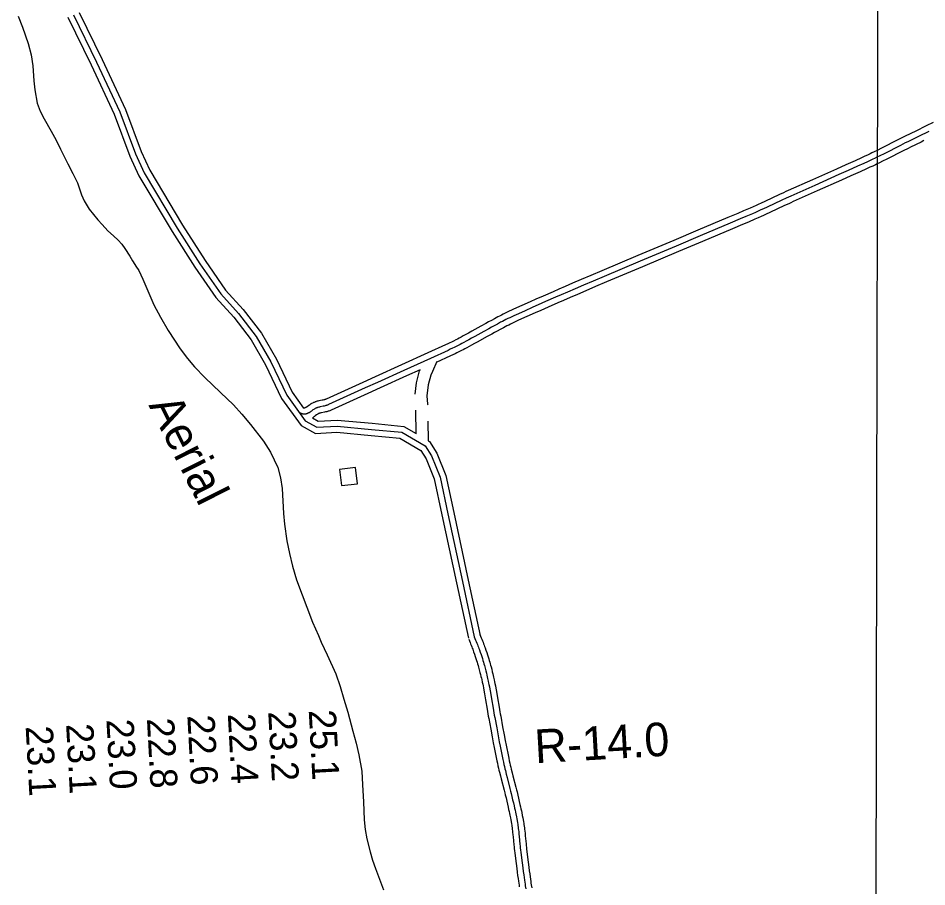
# Model space of a CAD drawing. Extents: x 3192952 to 3230831, y 849296 to 874698.
# Drawn here: x 3210734 to 3212978, y 863672 to 865816 of the extents above; entities that cross this region are included whole.
import ezdxf

# ---------------------------------------------------------------- set-up
doc = ezdxf.new("R2010")
doc.units = 0
for name, color, linetype in [('V-BLDG-OTLN', 7, 'Continuous'), ('V-GRID-MAJR', 7, 'Continuous'), ('V-RIVR-IDEN', 7, 'Continuous'), ('V-RIVR-RANG', 7, 'Continuous'), ('V-RIVR-RANG-IDEN', 7, 'Continuous'), ('V-ROAD-CNTR', 7, 'Continuous'), ('V-SITE-VEGE', 7, 'Continuous'), ('V-TOPO-SHOR', 7, 'Continuous')]:
    doc.layers.add(name, color=color, linetype=linetype)

msp = doc.modelspace()

# ---------------------------------------------------------------- linework, layer by layer
at = {"layer": 'V-BLDG-OTLN'}
msp.add_lwpolyline([(3211532.2, 864662), (3211571.9, 864666.8), (3211567.2, 864706.5), (3211527.4, 864701.7)], close=True, dxfattribs=at)
at = {"layer": 'V-GRID-MAJR'}
msp.add_spline([(3212836, 854703.6), (3212847.5, 860762.7), (3212858.9, 866825.2), (3212870.4, 872887.8), (3212870.4, 872891.2)], degree=3, dxfattribs=at)
at = {"layer": 'V-ROAD-CNTR'}
for p, q in [((3211715.3, 864847.9), (3211716.1, 864790.2)), ((3211745.6, 864821.4), (3211746.4, 864772.8))]:
    msp.add_line(p, q, dxfattribs=at)
for points in [[(3210884.3, 865829.6), (3210941.1, 865713.7), (3210999, 865590.2), (3211037.4, 865487), (3211058.8, 865440.8), (3211139.4, 865305.1), (3211195.4, 865217.9), (3211246, 865144.7), (3211289.3, 865096.8), (3211334.5, 865038.2), (3211371.5, 864974.3), (3211410.2, 864892.6), (3211438.8, 864853.2)], [(3210856.7, 865817.8), (3210914, 865700.8), (3210971.3, 865578.6), (3211009.7, 865475.4), (3211032.2, 865426.8), (3211113.9, 865289.3), (3211170.5, 865201.3), (3211222.4, 865126), (3211266.2, 865077.5), (3211309.5, 865021.5), (3211344.9, 864960.3), (3211384.3, 864877.2), (3211432.4, 864810.8), (3211467.9, 864790.9), (3211521, 864793.6), (3211605.2, 864786), (3211676.5, 864778.9), (3211728, 864748.7), (3211741.2, 864728.5), (3211761.2, 864678.5), (3211780, 864589.7), (3211816.1, 864422.2), (3211845.6, 864285.6)], [(3210870.5, 865823.7), (3210927.6, 865707.3), (3210985.2, 865584.4), (3211023.5, 865481.2), (3211045.5, 865433.8), (3211126.6, 865297.2), (3211182.9, 865209.6), (3211234.2, 865135.3), (3211277.8, 865087.2), (3211322, 865029.8), (3211358.2, 864967.3), (3211397.3, 864884.9), (3211442.6, 864822.3), (3211471.4, 864806.1), (3211521.3, 864808.6), (3211606.6, 864800.9), (3211681.3, 864793.6), (3211738.7, 864759.9), (3211754.6, 864735.5), (3211775.6, 864682.9), (3211794.7, 864592.8), (3211830.8, 864425.4), (3211860.2, 864288.8)], [(3212993.4, 865558), (3212976, 865549.6), (3212950, 865537), (3212924, 865524.2), (3212917.7, 865521.1), (3212906, 865515.2), (3212865.3, 865494.6), (3212855.1, 865489.5), (3212847.5, 865485.8), (3212841.8, 865483), (3212837.5, 865481), (3212831.1, 865477.9), (3212824.6, 865474.9), (3212815.9, 865470.9), (3212800.5, 865464), (3212777.4, 865453.6), (3212754.2, 865443.3), (3212694.9, 865416.8), (3212635.5, 865390.3), (3212629.5, 865387.6), (3212623.9, 865385), (3212613.4, 865380.2), (3212577.2, 865363.2), (3212568.2, 865359), (3212561.4, 865355.9), (3212556.4, 865353.6), (3212548.8, 865350.2), (3212541.1, 865346.9), (3212525, 865340), (3212510.9, 865334), (3212486.2, 865323.5), (3212449.1, 865307.8), (3212412, 865292.1), (3212352.8, 865267.1), (3212263.9, 865229.7), (3212175.1, 865192.3), (3212147.7, 865180.7), (3212123.8, 865170.5), (3212102.9, 865161.6), (3212084.7, 865153.7), (3212068.7, 865146.8), (3212054.7, 865140.7), (3212030.3, 865130), (3212012.1, 865121.9), (3211998.3, 865115.9), (3211977.8, 865106.7), (3211957.3, 865097.5), (3211951.8, 865095), (3211946.4, 865092.5), (3211941.3, 865090), (3211936.4, 865087.6), (3211931.6, 865085.2), (3211927, 865082.9), (3211922.6, 865080.6), (3211918.3, 865078.4), (3211910.1, 865074), (3211902.4, 865069.9), (3211895.2, 865066), (3211888.5, 865062.3), (3211876.1, 865055.3), (3211854.4, 865043.2), (3211846.3, 865038.7), (3211839.2, 865034.8), (3211833, 865031.5), (3211827.5, 865028.6), (3211822.8, 865026.1), (3211818.6, 865023.9), (3211815, 865022), (3211808.5, 865018.8), (3211803.7, 865016.4), (3211800.1, 865014.7), (3211794.7, 865012.1), (3211789.2, 865009.6), (3211745.7, 864989.8), (3211680.4, 864960.2), (3211615.1, 864930.6), (3211584.9, 864916.8), (3211539.6, 864896.2), (3211494.3, 864875.5), (3211493.8, 864875.3), (3211492.6, 864874.9), (3211491.3, 864874.4)], [(3212982.6, 865536.1), (3212956.6, 865523.5), (3212930.7, 865510.8), (3212924.4, 865507.7), (3212912.8, 865501.8), (3212872, 865481.2), (3212861.8, 865476.1), (3212854.1, 865472.3), (3212848.3, 865469.5), (3212844, 865467.4), (3212837.4, 865464.3), (3212830.9, 865461.3), (3212822.1, 865457.3), (3212806.7, 865450.3), (3212783.5, 865440), (3212760.4, 865429.6), (3212701, 865403.1), (3212641.6, 865376.6), (3212635.7, 865373.9), (3212630.2, 865371.4), (3212619.8, 865366.6), (3212583.5, 865349.6), (3212574.5, 865345.4), (3212567.6, 865342.3), (3212562.5, 865339.9), (3212554.8, 865336.5), (3212547.1, 865333.1), (3212530.9, 865326.2), (3212516.8, 865320.2), (3212492.1, 865309.6), (3212454.9, 865294), (3212417.8, 865278.3), (3212358.6, 865253.3), (3212269.7, 865215.9), (3212180.9, 865178.5), (3212153.6, 865166.9), (3212129.7, 865156.7), (3212108.9, 865147.8), (3212090.6, 865139.9), (3212074.7, 865133), (3212060.8, 865127), (3212036.4, 865116.3), (3212018.1, 865108.2), (3212004.4, 865102.2), (3211983.9, 865093), (3211963.4, 865083.8), (3211958, 865081.4), (3211952.8, 865078.9), (3211947.8, 865076.5), (3211943, 865074.2), (3211938.3, 865071.8), (3211933.8, 865069.5), (3211929.5, 865067.3), (3211925.3, 865065.1), (3211917.1, 865060.8), (3211909.6, 865056.7), (3211902.5, 865052.8), (3211895.8, 865049.1), (3211883.4, 865042.2), (3211861.7, 865030.1), (3211853.5, 865025.6), (3211846.4, 865021.6), (3211840.1, 865018.3), (3211834.6, 865015.3), (3211829.7, 865012.8), (3211825.5, 865010.6), (3211821.8, 865008.7), (3211815.2, 865005.4), (3211810.3, 865002.9), (3211806.6, 865001.1), (3211801, 864998.5), (3211795.4, 864995.9), (3211751.9, 864976.1), (3211686.6, 864946.5), (3211621.3, 864916.9), (3211591.1, 864903.2), (3211545.8, 864882.5), (3211500.4, 864861.9), (3211499.6, 864861.5), (3211498, 864860.8), (3211496.4, 864860.3)], [(3212970.2, 865513.4), (3212963.2, 865510), (3212937.3, 865497.3), (3212931.1, 865494.3), (3212919.5, 865488.5), (3212878.7, 865467.8), (3212868.4, 865462.6), (3212860.7, 865458.8), (3212854.8, 865456), (3212850.4, 865453.9), (3212843.8, 865450.7), (3212837.1, 865447.7), (3212828.3, 865443.6), (3212812.8, 865436.6), (3212789.6, 865426.3), (3212766.5, 865415.9), (3212707.1, 865389.4), (3212647.8, 865362.9), (3212641.9, 865360.2), (3212636.4, 865357.7), (3212626.1, 865353), (3212589.9, 865336), (3212580.7, 865331.8), (3212573.9, 865328.6), (3212568.7, 865326.3), (3212560.9, 865322.8), (3212553, 865319.4), (3212536.9, 865312.4), (3212522.7, 865306.4), (3212497.9, 865295.8), (3212460.8, 865280.1), (3212423.6, 865264.5), (3212364.4, 865239.5), (3212275.6, 865202.1), (3212186.7, 865164.7), (3212159.5, 865153.1), (3212135.6, 865143), (3212114.8, 865134), (3212096.6, 865126.2), (3212080.7, 865119.3), (3212066.8, 865113.2), (3212042.4, 865102.5), (3212024.2, 865094.5), (3212010.5, 865088.5), (3211990, 865079.3), (3211969.6, 865070.2), (3211964.3, 865067.8), (3211959.3, 865065.4), (3211954.4, 865063), (3211949.6, 865060.7), (3211945.1, 865058.4), (3211940.7, 865056.2), (3211936.4, 865054), (3211932.2, 865051.8), (3211924.2, 865047.6), (3211916.7, 865043.5), (3211909.7, 865039.7), (3211903.1, 865036), (3211890.7, 865029.1), (3211869, 865017), (3211860.7, 865012.4), (3211853.5, 865008.5), (3211847.2, 865005), (3211841.6, 865002.1), (3211836.7, 864999.5), (3211832.4, 864997.2), (3211828.5, 864995.3), (3211821.9, 864991.9), (3211816.9, 864989.5), (3211813.1, 864987.6), (3211807.4, 864984.9), (3211801.7, 864982.3), (3211765.7, 864965.9)], [(3211767.4, 864968.4), (3211756.7, 864943.4), (3211752.6, 864935), (3211746.2, 864910.4), (3211743.1, 864883.5), (3211745, 864863), (3211745.1, 864861.4)], [(3211726.2, 864948), (3211692.8, 864932.9), (3211627.5, 864903.3), (3211597.3, 864889.5), (3211552, 864868.9), (3211506.6, 864848.2), (3211505.4, 864847.7), (3211503.3, 864846.8), (3211501.4, 864846.1)], [(3211725.4, 864947.7), (3211724.4, 864945.5), (3211716.6, 864915.9), (3211713.4, 864887.8)], [(3211491.8, 864874.5), (3211490.5, 864874.1), (3211489.4, 864873.8), (3211488.4, 864873.5), (3211486.2, 864873), (3211484.3, 864872.6), (3211476.5, 864871), (3211474.3, 864870.5), (3211472.6, 864870.1), (3211470.1, 864869.4), (3211468.7, 864869), (3211467.3, 864868.6), (3211466.1, 864868.1), (3211464.8, 864867.6), (3211463.6, 864867.1), (3211462.4, 864866.6), (3211460.4, 864865.6), (3211458.6, 864864.5), (3211457, 864863.6), (3211455.6, 864862.6), (3211453.2, 864861), (3211449.5, 864858.3), (3211448.2, 864857.4), (3211447.2, 864856.6), (3211446.3, 864856.1), (3211445.7, 864855.6), (3211444.5, 864854.9), (3211443.8, 864854.5), (3211443.3, 864854.2), (3211443, 864854.1), (3211442.6, 864853.9), (3211442.1, 864853.7), (3211442.1, 864853.7), (3211442.2, 864853.7), (3211441.8, 864853.6), (3211441.6, 864853.6), (3211438.8, 864853.2)], [(3211496.4, 864860.3), (3211494.9, 864859.8), (3211493.5, 864859.4), (3211492.2, 864859), (3211489.6, 864858.4), (3211487.4, 864857.9), (3211479.6, 864856.3), (3211477.7, 864855.9), (3211476.3, 864855.5), (3211474.2, 864855), (3211473.1, 864854.7), (3211472.1, 864854.3), (3211471.2, 864854), (3211470.4, 864853.7), (3211469.7, 864853.4), (3211468.9, 864853.1), (3211467.5, 864852.3), (3211466.2, 864851.6), (3211465, 864850.9), (3211463.9, 864850.2), (3211461.9, 864848.7), (3211458.3, 864846.1), (3211456.9, 864845.2), (3211455.8, 864844.4), (3211454.8, 864843.6), (3211453.9, 864843), (3211452.3, 864842.1), (3211451.1, 864841.4), (3211450.2, 864840.9), (3211449.5, 864840.5), (3211448.5, 864840.1), (3211447.4, 864839.7), (3211446.9, 864839.5), (3211446.3, 864839.3), (3211445.2, 864839), (3211444.1, 864838.8), (3211443, 864838.6), (3211442, 864838.5), (3211441.1, 864838.5), (3211440.2, 864838.5), (3211439.3, 864838.5), (3211438.5, 864838.6), (3211437.7, 864838.7), (3211437, 864838.8), (3211436.4, 864838.9), (3211435.1, 864839.2), (3211434.1, 864839.5), (3211433.2, 864839.8), (3211432.4, 864840.1), (3211431.7, 864840.4), (3211431.1, 864840.7), (3211430.1, 864841.3), (3211429.4, 864841.7), (3211428.8, 864842.1), (3211428.1, 864842.7), (3211427.3, 864843.3)], [(3211501, 864846), (3211499.3, 864845.4), (3211497.5, 864844.9), (3211495.9, 864844.5), (3211493, 864843.8), (3211490.5, 864843.2), (3211482.8, 864841.6), (3211481.1, 864841.3), (3211480, 864841), (3211478.2, 864840.5), (3211477.5, 864840.3), (3211476.8, 864840.1), (3211476.4, 864840), (3211476.1, 864839.8), (3211475.8, 864839.7), (3211475.5, 864839.6), (3211474.6, 864839.1), (3211473.9, 864838.7), (3211473, 864838.2), (3211472.2, 864837.7), (3211470.5, 864836.5), (3211467.1, 864834), (3211465.7, 864833), (3211464.4, 864832.1), (3211463.2, 864831.2), (3211462, 864830.5), (3211460.4, 864829.5)], [(3211460.4, 864829.5), (3211475, 864821.3), (3211521.6, 864823.7), (3211608, 864815.9), (3211686, 864808.2), (3211716.5, 864790.3)], [(3211746.4, 864772.7), (3211749.3, 864771), (3211768, 864742.4), (3211790.1, 864687.2), (3211809.3, 864595.9), (3211845.4, 864428.5), (3211874.9, 864292)], [(3211846.4, 864282.9), (3211848.1, 864279), (3211849.7, 864275.2), (3211851.2, 864271.6), (3211852.6, 864268), (3211853.9, 864264.6), (3211855.2, 864261.3), (3211856.4, 864258.1), (3211857.5, 864255), (3211858.6, 864252), (3211860.7, 864246.1), (3211862.6, 864240.7), (3211864.3, 864235.5), (3211865.8, 864230.7), (3211867.2, 864226.2), (3211868.5, 864222), (3211869.7, 864218), (3211870.7, 864214.2), (3211871.7, 864210.7), (3211872.6, 864207.4), (3211874.2, 864201.2), (3211875.6, 864195.8), (3211876.7, 864191), (3211877.7, 864186.8), (3211878.5, 864183.2), (3211879.9, 864176.7), (3211880.9, 864171.9), (3211881.7, 864168.3), (3211882.7, 864162.8), (3211883.7, 864157.2), (3211885.2, 864148.6), (3211887.8, 864133.4), (3211891.7, 864110.4), (3211893.8, 864098.9), (3211894.8, 864093.1), (3211895.9, 864087.4), (3211900.7, 864061.3), (3211904.4, 864041.8), (3211907.1, 864027.1), (3211909.3, 864016.1), (3211910.9, 864007.8), (3211913.4, 863995.4), (3211915.9, 863983), (3211917.3, 863976.7), (3211918.6, 863970.7), (3211919.9, 863965.1), (3211921.1, 863960), (3211922.3, 863955.1), (3211924.6, 863946), (3211926.6, 863938.1), (3211933.6, 863910.7), (3211935.4, 863903.9), (3211936.6, 863898.9), (3211938.5, 863891.2), (3211940.3, 863883.6), (3211942.1, 863875.7), (3211943.7, 863868.9), (3211945, 863862.9), (3211946.1, 863857.6), (3211947.1, 863853.1), (3211947.9, 863849.1), (3211949.3, 863842.1), (3211950.3, 863836.9), (3211951, 863833), (3211952.1, 863827.1), (3211952.5, 863824.2), (3211953, 863821.3), (3211953.6, 863817.3), (3211954.1, 863813.6), (3211954.5, 863810.1), (3211954.9, 863806.8), (3211955.6, 863800.5), (3211956.1, 863795), (3211958, 863775.4), (3211958.5, 863770.5), (3211958.9, 863766.7), (3211959.5, 863761.1), (3211960.2, 863755.5), (3211961.9, 863741.5), (3211965, 863717), (3211966.2, 863707.7), (3211967.2, 863699.6), (3211968.2, 863692.6), (3211969.1, 863686.3), (3211969.9, 863680.9), (3211970.6, 863676.1), (3211971.2, 863672)], [(3211860.2, 864288.8), (3211861.9, 864284.8), (3211863.5, 864280.9), (3211865.1, 864277.2), (3211866.5, 864273.6), (3211867.9, 864270.1), (3211869.2, 864266.7), (3211870.4, 864263.4), (3211871.6, 864260.2), (3211872.8, 864257.1), (3211874.9, 864251.1), (3211876.8, 864245.5), (3211878.5, 864240.2), (3211880.1, 864235.2), (3211881.6, 864230.6), (3211882.9, 864226.2), (3211884.1, 864222.1), (3211885.2, 864218.3), (3211886.2, 864214.7), (3211887.1, 864211.3), (3211888.8, 864204.9), (3211890.2, 864199.4), (3211891.3, 864194.5), (3211892.3, 864190.2), (3211893.2, 864186.4), (3211894.6, 864179.8), (3211895.6, 864174.9), (3211896.4, 864171.1), (3211897.5, 864165.5), (3211898.5, 864159.9), (3211900, 864151.2), (3211902.6, 864135.9), (3211906.5, 864113), (3211908.5, 864101.5), (3211909.6, 864095.8), (3211910.6, 864090.1), (3211915.5, 864064.1), (3211919.1, 864044.5), (3211921.9, 864029.9), (3211924, 864019), (3211925.6, 864010.7), (3211928.1, 863998.4), (3211930.6, 863986.1), (3211931.9, 863979.9), (3211933.2, 863974), (3211934.5, 863968.6), (3211935.7, 863963.5), (3211936.9, 863958.7), (3211939.1, 863949.7), (3211941.1, 863941.9), (3211948.2, 863914.5), (3211949.9, 863907.6), (3211951.2, 863902.5), (3211953.1, 863894.7), (3211954.9, 863887), (3211956.7, 863879.1), (3211958.3, 863872.2), (3211959.6, 863866.1), (3211960.8, 863860.8), (3211961.8, 863856.2), (3211962.6, 863852.1), (3211964.1, 863845), (3211965.1, 863839.6), (3211965.8, 863835.6), (3211966.9, 863829.6), (3211967.3, 863826.5), (3211967.8, 863823.5), (3211968.4, 863819.4), (3211968.9, 863815.5), (3211969.4, 863811.9), (3211969.8, 863808.5), (3211970.5, 863802.1), (3211971.1, 863796.5), (3211972.9, 863776.9), (3211973.4, 863772), (3211973.8, 863768.3), (3211974.4, 863762.8), (3211975.1, 863757.3), (3211976.8, 863743.3), (3211979.9, 863718.8), (3211981, 863709.7), (3211982.1, 863701.6), (3211983, 863694.6), (3211983.9, 863688.5), (3211984.7, 863683.1), (3211985.4, 863678.4), (3211986.1, 863674.3)], [(3211874, 864294.7), (3211875.7, 864290.6), (3211877.4, 864286.7), (3211879, 864282.8), (3211880.5, 864279.1), (3211881.9, 864275.5), (3211883.2, 864272), (3211884.5, 864268.6), (3211885.7, 864265.3), (3211886.9, 864262.1), (3211889, 864256), (3211891, 864250.2), (3211892.8, 864244.8), (3211894.4, 864239.7), (3211895.9, 864235), (3211897.3, 864230.5), (3211898.5, 864226.3), (3211899.6, 864222.3), (3211900.6, 864218.6), (3211901.6, 864215.2), (3211903.3, 864208.7), (3211904.7, 864202.9), (3211905.9, 864197.9), (3211906.9, 864193.5), (3211907.8, 864189.7), (3211909.3, 864182.9), (3211910.3, 864177.8), (3211911.1, 864174), (3211912.2, 864168.3), (3211913.2, 864162.5), (3211914.8, 864153.7), (3211917.4, 864138.4), (3211921.3, 864115.5), (3211923.3, 864104.1), (3211924.3, 864098.5), (3211925.4, 864092.8), (3211930.2, 864066.8), (3211933.8, 864047.3), (3211936.6, 864032.7), (3211938.7, 864021.8), (3211940.3, 864013.6), (3211942.8, 864001.4), (3211945.3, 863989.2), (3211946.6, 863983.1), (3211947.8, 863977.4), (3211949.1, 863972), (3211950.3, 863967), (3211951.4, 863962.3), (3211953.6, 863953.4), (3211955.6, 863945.6), (3211962.7, 863918.2), (3211964.5, 863911.3), (3211965.8, 863906), (3211967.7, 863898.2), (3211969.5, 863890.4), (3211971.3, 863882.4), (3211972.9, 863875.5), (3211974.3, 863869.3), (3211975.5, 863864), (3211976.5, 863859.3), (3211977.3, 863855.1), (3211978.8, 863847.9), (3211979.8, 863842.4), (3211980.6, 863838.2), (3211981.6, 863832), (3211982.2, 863828.9), (3211982.6, 863825.7), (3211983.3, 863821.5), (3211983.8, 863817.5), (3211984.3, 863813.7), (3211984.7, 863810.2), (3211985.4, 863803.7), (3211986, 863798), (3211987.9, 863778.3), (3211988.3, 863773.5), (3211988.7, 863769.9), (3211989.3, 863764.6), (3211990, 863759.2), (3211991.7, 863745.2), (3211994.7, 863720.7), (3211995.9, 863711.6), (3211997, 863703.6), (3211997.9, 863696.7), (3211998.8, 863690.6), (3211999.5, 863685.3), (3212000.2, 863680.7), (3212000.9, 863676.6)], [(3212000.9, 863676.7), (3212002, 863669.6)], [(3211986.1, 863674.3), (3211987.2, 863667.2)]]:
    msp.add_lwpolyline(points, dxfattribs=at)
at = {"layer": 'V-SITE-VEGE'}
for p, q in [((3210734, 865820.6), (3210744.7, 865793.7)), ((3210744.7, 865793.7), (3210758.6, 865753.3)), ((3210758.6, 865753.3), (3210766.3, 865725.1)), ((3210766.3, 865725.1), (3210770.2, 865698.2)), ((3210770.2, 865698.2), (3210773, 865660.7)), ((3210773, 865660.7), (3210775.1, 865638.7)), ((3210775.1, 865638.7), (3210781, 865605.6)), ((3210781, 865605.6), (3210788.5, 865586)), ((3210788.5, 865586), (3210797.9, 865567.1)), ((3210797.9, 865567.1), (3210815.4, 865537.1)), ((3210815.4, 865537.1), (3210827.9, 865514.6)), ((3210827.9, 865514.6), (3210838.5, 865492.6)), ((3210838.5, 865492.6), (3210856.7, 865456.5)), ((3210856.7, 865456.5), (3210868.6, 865432.1)), ((3210868.6, 865432.1), (3210880.5, 865409.5)), ((3210880.5, 865409.5), (3210890.6, 865379.5)), ((3210890.6, 865379.5), (3210896.9, 865364.8)), ((3210896.9, 865364.8), (3210909.4, 865344.7)), ((3210909.4, 865344.7), (3210931.1, 865317.9)), ((3210931.1, 865317.9), (3210941.1, 865306.3)), ((3210941.1, 865306.3), (3210955.3, 865291.1)), ((3210955.3, 865291.1), (3210969, 865278.3)), ((3210969, 865278.3), (3210980.7, 865268)), ((3210980.7, 865268), (3210990, 865257.7)), ((3210990, 865257.7), (3210997.5, 865247.3)), ((3210997.5, 865247.3), (3211009.4, 865228.4)), ((3211009.4, 865228.4), (3211016.2, 865216.8)), ((3211016.2, 865216.8), (3211026.2, 865200.9)), ((3211026.2, 865200.9), (3211029.9, 865195.4)), ((3211029.9, 865195.4), (3211031.8, 865193)), ((3211031.8, 865193), (3211041.8, 865171.6)), ((3211041.8, 865171.6), (3211068.9, 865108)), ((3211068.9, 865108), (3211085.1, 865078.1)), ((3211085.1, 865078.1), (3211104.5, 865044.5)), ((3211104.5, 865044.5), (3211133.8, 864999.4)), ((3211133.8, 864999.4), (3211151.8, 864975.6)), ((3211151.8, 864975.6), (3211169.2, 864954.9)), ((3211169.2, 864954.9), (3211194.6, 864928.8)), ((3211194.6, 864928.8), (3211233.7, 864891.7)), ((3211233.7, 864891.7), (3211265.3, 864861.3)), ((3211265.3, 864861.3), (3211286.4, 864838.2)), ((3211286.4, 864838.2), (3211307.5, 864812.6)), ((3211307.5, 864812.6), (3211339.8, 864771.8)), ((3211339.8, 864771.8), (3211357.3, 864745)), ((3211357.3, 864745), (3211374.9, 864706.5)), ((3211374.9, 864706.5), (3211381.9, 864681.3)), ((3211381.9, 864681.3), (3211385.8, 864655)), ((3211385.8, 864655), (3211389.5, 864593)), ((3211389.5, 864593), (3211391.6, 864566.6)), ((3211391.6, 864566.6), (3211397.5, 864525.6)), ((3211397.5, 864525.6), (3211404, 864494.9)), ((3211404, 864494.9), (3211411.6, 864463.1)), ((3211411.6, 864463.1), (3211421.2, 864429.4)), ((3211421.2, 864429.4), (3211460.9, 864325.4)), ((3211460.9, 864325.4), (3211475.3, 864292.4)), ((3211475.3, 864292.4), (3211482.2, 864275.9)), ((3211482.2, 864275.9), (3211497.3, 864244.7)), ((3211497.3, 864244.7), (3211518, 864197.7)), ((3211518, 864197.7), (3211528.7, 864166.5)), ((3211528.7, 864166.5), (3211538.3, 864135.2)), ((3211538.3, 864135.2), (3211547.8, 864102.8)), ((3211547.8, 864102.8), (3211560.5, 864056.3)), ((3211560.5, 864056.3), (3211568.2, 864026.3)), ((3211568.2, 864026.3), (3211575.2, 863997.5)), ((3211575.2, 863997.5), (3211582.4, 863957.6)), ((3211582.4, 863957.6), (3211583.9, 863923.3)), ((3211583.9, 863923.3), (3211586.8, 863881.5)), ((3211586.8, 863881.5), (3211588.5, 863837.4)), ((3211588.5, 863837.4), (3211591.1, 863813.4)), ((3211591.1, 863813.4), (3211595.1, 863790.2)), ((3211595.1, 863790.2), (3211602.7, 863758.3)), ((3211602.7, 863758.3), (3211609.1, 863738.1)), ((3211609.1, 863738.1), (3211616, 863717.3)), ((3211616, 863717.3), (3211636.2, 863664.7))]:
    msp.add_line(p, q, dxfattribs=at)
at = {"layer": 'V-TOPO-SHOR'}
msp.add_lwpolyline([(3210734, 865820.6), (3210744.7, 865793.7), (3210758.6, 865753.3), (3210766.3, 865725.1), (3210770.2, 865698.2), (3210773, 865660.7), (3210775.1, 865638.7), (3210781, 865605.6), (3210788.5, 865586), (3210797.9, 865567.1), (3210815.4, 865537.1), (3210827.9, 865514.6), (3210838.5, 865492.6), (3210856.7, 865456.5), (3210868.6, 865432.1), (3210880.5, 865409.5), (3210890.6, 865379.5), (3210896.9, 865364.8), (3210909.4, 865344.7), (3210931.1, 865317.9), (3210941.1, 865306.3), (3210955.3, 865291.1), (3210969, 865278.3), (3210980.7, 865268), (3210990, 865257.7), (3210997.5, 865247.3), (3211009.4, 865228.4), (3211016.2, 865216.8), (3211026.2, 865200.9), (3211029.9, 865195.4), (3211031.8, 865193), (3211041.8, 865171.6), (3211068.9, 865108), (3211085.1, 865078.1), (3211104.5, 865044.5), (3211133.8, 864999.4), (3211151.8, 864975.6), (3211169.2, 864954.9), (3211194.6, 864928.8), (3211233.7, 864891.7), (3211265.3, 864861.3), (3211286.4, 864838.2), (3211307.5, 864812.6), (3211339.8, 864771.8), (3211357.3, 864745), (3211374.9, 864706.5), (3211381.9, 864681.3), (3211385.8, 864655), (3211389.5, 864593), (3211391.6, 864566.6), (3211397.5, 864525.6), (3211404, 864494.9), (3211411.6, 864463.1), (3211421.2, 864429.4), (3211460.9, 864325.4), (3211475.3, 864292.4), (3211482.2, 864275.9), (3211497.3, 864244.7), (3211518, 864197.7), (3211528.7, 864166.5), (3211538.3, 864135.2), (3211547.8, 864102.8), (3211560.5, 864056.3), (3211568.2, 864026.3), (3211575.2, 863997.5), (3211582.4, 863957.6), (3211583.9, 863923.3), (3211586.8, 863881.5), (3211588.5, 863837.4), (3211591.1, 863813.4), (3211595.1, 863790.2), (3211602.7, 863758.3), (3211609.1, 863738.1), (3211616, 863717.3), (3211636.2, 863664.7)], dxfattribs=at)

# ---------------------------------------------------------------- texts
at = {"layer": 'V-RIVR-IDEN'}
msp.add_text('Aerial', height=83, rotation=296.7891, dxfattribs=at).set_placement((3211055.1, 864860.5))
at = {"layer": 'V-RIVR-RANG'}
for s, p in [('23.2', (3211351.3, 864104.4)), ('25.1', (3211451.3, 864107.8)), ('23.0', (3210951.8, 864084.5)), ('22.8', (3211051.8, 864087.3)), ('22.6', (3211151.6, 864094.9)), ('22.4', (3211251.5, 864098.7)), ('23.1', (3210752.4, 864067.8)), ('23.1', (3210852.3, 864073.5))]:
    msp.add_text(s, height=67, rotation=273.1283, dxfattribs=at).set_placement(p)
at = {"layer": 'V-RIVR-RANG-IDEN'}
msp.add_text('R-14.0', height=83, rotation=3.2736, dxfattribs=at).set_placement((3212011.3, 863976.9))

doc.saveas('drawing.dxf')
